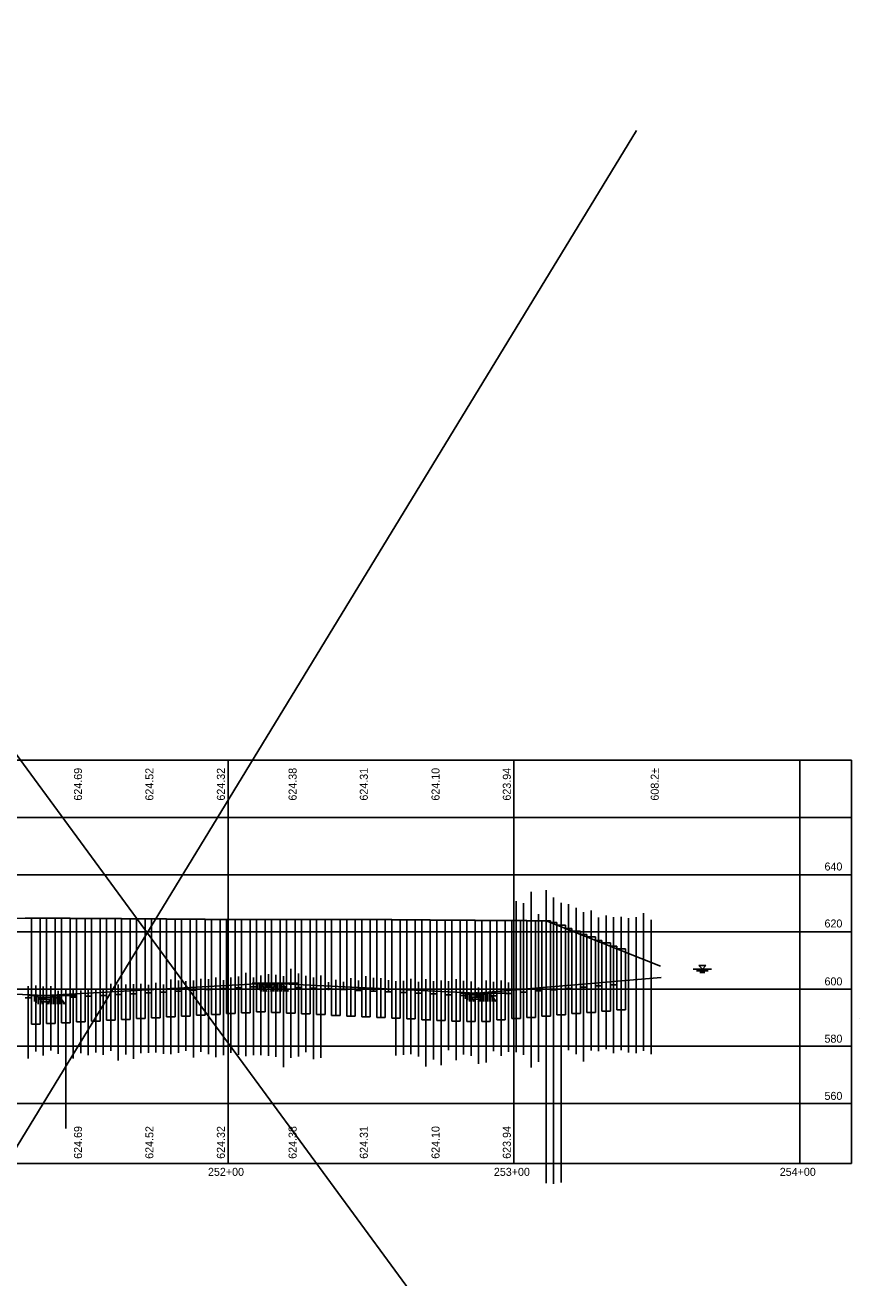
# Model space of a CAD drawing. Extents: x 2267596 to 2268160, y 712626 to 714793.
# Drawn here: x 2267867.7 to 2268159.8, y 712887.4 to 713325.6 of the extents above; entities that cross this region are included whole.
import ezdxf

# ---------------------------------------------------------------- set-up
doc = ezdxf.new("R2010")
doc.units = 0
for name, color, linetype in [('BR_P_Gen_Text', 7, 'Continuous'), ('BR_P_Sub_Deep_Object', 7, 'Continuous'), ('Default', 7, 'Continuous'), ('GE_X_Alignment', 7, 'Continuous'), ('PF_X_Ground_Line', 7, 'Continuous'), ('SC_Scratch1', 7, 'Continuous'), ('SC_Scratch9', 7, 'Continuous'), ('SH_Major_Grid_Line', 7, 'Continuous'), ('UT_P_Water_Cells', 7, 'Continuous'), ('XS_X_Ground_Line', 7, 'Continuous')]:
    doc.layers.add(name, color=color, linetype=linetype)

msp = doc.modelspace()

# ---------------------------------------------------------------- linework, layer by layer
at = {"layer": 'BR_P_Sub_Deep_Object'}
for p, q in [((2267867.74, 713013.25), (2267869.99, 713013.25)), ((2267869.99, 713013.25), (2267869.99, 712976.15)), ((2267869.99, 713013.23), (2267872.99, 713013.23)), ((2267872.99, 713013.23), (2267872.99, 712976.15)), ((2267872.99, 713013.21), (2267875.24, 713013.21)), ((2267875.24, 713013.21), (2267875.24, 712976.32)), ((2267875.24, 713013.2), (2267878.24, 713013.2)), ((2267878.24, 713013.2), (2267878.24, 712976.32)), ((2267878.24, 713013.18), (2267880.49, 713013.18)), ((2267880.49, 713013.18), (2267880.49, 712976.62)), ((2267880.49, 713013.17), (2267883.49, 713013.17)), ((2267883.49, 713013.17), (2267883.49, 712976.62)), ((2267883.49, 713013.15), (2267885.74, 713013.15)), ((2267885.74, 713013.15), (2267885.74, 712976.91)), ((2267885.74, 713013.14), (2267888.74, 713013.14)), ((2267888.74, 713013.14), (2267888.74, 712976.91)), ((2267888.74, 713013.12), (2267890.99, 713013.12)), ((2267890.99, 713013.12), (2267890.99, 712977.21)), ((2267890.99, 713013.1), (2267893.99, 713013.1)), ((2267893.99, 713013.1), (2267893.99, 712977.21)), ((2267893.99, 713013.08), (2267896.24, 713013.08)), ((2267896.24, 713013.08), (2267896.24, 712977.5)), ((2267896.24, 713013.07), (2267899.24, 713013.07)), ((2267899.24, 713013.07), (2267899.24, 712977.5)), ((2267899.24, 713013.05), (2267901.49, 713013.05)), ((2267901.49, 713013.05), (2267901.49, 712977.8)), ((2267901.49, 713013.03), (2267904.49, 713013.03)), ((2267904.49, 713013.03), (2267904.49, 712977.8)), ((2267904.49, 713013.01), (2267906.74, 713013.01)), ((2267906.74, 713013.01), (2267906.74, 712978.1)), ((2267906.74, 713013), (2267909.74, 713013)), ((2267909.74, 713013), (2267909.74, 712978.1)), ((2267909.74, 713012.98), (2267911.99, 713012.98)), ((2267911.99, 713012.98), (2267911.99, 712978.39)), ((2267911.99, 713012.96), (2267914.99, 713012.96)), ((2267914.99, 713012.96), (2267914.99, 712978.39)), ((2267914.99, 713012.94), (2267917.24, 713012.94)), ((2267917.24, 713012.94), (2267917.24, 712978.69)), ((2267917.24, 713012.92), (2267920.24, 713012.92)), ((2267920.24, 713012.92), (2267920.24, 712978.69)), ((2267920.24, 713012.9), (2267922.49, 713012.9)), ((2267922.49, 713012.9), (2267922.49, 712978.98)), ((2267922.49, 713012.88), (2267925.49, 713012.88)), ((2267925.49, 713012.88), (2267925.49, 712978.98)), ((2267925.49, 713012.86), (2267927.74, 713012.86)), ((2267927.74, 713012.86), (2267927.74, 712979.28)), ((2267927.74, 713012.84), (2267930.74, 713012.84)), ((2267930.74, 713012.84), (2267930.74, 712979.28)), ((2267930.74, 713012.81), (2267932.99, 713012.81)), ((2267932.99, 713012.81), (2267932.99, 712979.57)), ((2267932.99, 713012.8), (2267935.99, 713012.8)), ((2267935.99, 713012.8), (2267935.99, 712979.57)), ((2267935.99, 713012.77), (2267938.24, 713012.77)), ((2267938.24, 713012.77), (2267938.24, 712979.87)), ((2267938.24, 713012.76), (2267941.24, 713012.76)), ((2267941.24, 713012.76), (2267941.24, 712979.87)), ((2267941.24, 713012.76), (2267943.49, 713012.76)), ((2267943.49, 713012.77), (2267943.49, 712980.16)), ((2267943.49, 713012.77), (2267946.49, 713012.77)), ((2267946.49, 713012.77), (2267946.49, 712980.16)), ((2267946.49, 713012.77), (2267948.74, 713012.77)), ((2267948.74, 713012.78), (2267948.74, 712980.46)), ((2267948.74, 713012.78), (2267951.74, 713012.78)), ((2267951.74, 713012.79), (2267951.74, 712980.46)), ((2267951.74, 713012.79), (2267953.99, 713012.79)), ((2267953.99, 713012.79), (2267953.99, 712980.23)), ((2267953.99, 713012.79), (2267956.99, 713012.79)), ((2267956.99, 713012.8), (2267956.99, 712980.23)), ((2267956.99, 713012.8), (2267959.24, 713012.8)), ((2267959.24, 713012.81), (2267959.24, 712979.97)), ((2267959.24, 713012.81), (2267962.24, 713012.81)), ((2267962.24, 713012.81), (2267962.24, 712979.97)), ((2267962.24, 713012.81), (2267964.49, 713012.81)), ((2267964.49, 713012.81), (2267964.49, 712979.72)), ((2267964.49, 713012.81), (2267967.49, 713012.81)), ((2267967.49, 713012.81), (2267967.49, 712979.72)), ((2267967.49, 713012.8), (2267969.74, 713012.8)), ((2267969.74, 713012.8), (2267969.74, 712979.47)), ((2267969.74, 713012.79), (2267972.74, 713012.79)), ((2267972.74, 713012.79), (2267972.74, 712979.47)), ((2267972.74, 713012.78), (2267974.99, 713012.78)), ((2267974.99, 713012.78), (2267974.99, 712979.21)), ((2267974.99, 713012.78), (2267977.99, 713012.78)), ((2267977.99, 713012.78), (2267977.99, 712979.21)), ((2267977.99, 713012.77), (2267980.24, 713012.77)), ((2267980.24, 713012.77), (2267980.24, 712978.96)), ((2267980.24, 713012.76), (2267983.24, 713012.76)), ((2267983.24, 713012.76), (2267983.24, 712978.96)), ((2267983.24, 713012.75), (2267985.49, 713012.75)), ((2267985.49, 713012.75), (2267985.49, 712978.71)), ((2267985.49, 713012.75), (2267988.49, 713012.75)), ((2267988.49, 713012.75), (2267988.49, 712978.71)), ((2267988.49, 713012.74), (2267990.74, 713012.74)), ((2267990.74, 713012.74), (2267990.74, 712978.45)), ((2267990.74, 713012.72), (2267993.74, 713012.72)), ((2267993.74, 713012.72), (2267993.74, 712978.45)), ((2267993.74, 713012.7), (2267995.99, 713012.7)), ((2267995.99, 713012.7), (2267995.99, 712978.2)), ((2267995.99, 713012.68), (2267998.99, 713012.68)), ((2267998.99, 713012.68), (2267998.99, 712978.2)), ((2267998.99, 713012.65), (2268001.24, 713012.65)), ((2268001.24, 713012.65), (2268001.24, 712977.95)), ((2268001.24, 713012.63), (2268004.24, 713012.63)), ((2268004.24, 713012.63), (2268004.24, 712977.95)), ((2268004.24, 713012.61), (2268006.49, 713012.61)), ((2268006.49, 713012.61), (2268006.49, 712977.7)), ((2268006.49, 713012.59), (2268009.49, 713012.59)), ((2268009.49, 713012.59), (2268009.49, 712977.44)), ((2268009.49, 713012.57), (2268011.74, 713012.57)), ((2268011.74, 713012.57), (2268011.74, 712977.44)), ((2268011.74, 713012.55), (2268014.74, 713012.55)), ((2268014.74, 713012.55), (2268014.74, 712977.44)), ((2268014.74, 713012.52), (2268016.99, 713012.52)), ((2268016.99, 713012.52), (2268016.99, 712977.19)), ((2268016.99, 713012.51), (2268019.99, 713012.51)), ((2268019.99, 713012.51), (2268019.99, 712977.19)), ((2268019.99, 713012.49), (2268022.24, 713012.49)), ((2268022.24, 713012.49), (2268022.24, 712977.05)), ((2268022.24, 713012.48), (2268025.24, 713012.48)), ((2268025.24, 713012.48), (2268025.24, 712977.05)), ((2268025.24, 713012.46), (2268027.49, 713012.46)), ((2268027.49, 713012.46), (2268027.49, 712977.05)), ((2268027.49, 713012.44), (2268030.49, 713012.44)), ((2268030.49, 713012.44), (2268030.49, 712977.05)), ((2268030.49, 713012.42), (2268032.74, 713012.42)), ((2268032.74, 713012.42), (2268032.74, 712977.63)), ((2268032.74, 713012.41), (2268035.74, 713012.41)), ((2268035.74, 713012.41), (2268035.74, 712977.63)), ((2268035.74, 713012.39), (2268037.99, 713012.39)), ((2268037.99, 713012.39), (2268037.99, 712978.07)), ((2268037.99, 713012.37), (2268040.99, 713012.37)), ((2268040.99, 713012.37), (2268040.99, 712978.07)), ((2268040.99, 713012.36), (2268043.24, 713012.36)), ((2268043.24, 713012.36), (2268043.24, 712978.5)), ((2268043.24, 713012.34), (2268046.24, 713012.34)), ((2268046.24, 713012.34), (2268046.24, 712978.5)), ((2268046.24, 713012.32), (2268048.49, 713012.32)), ((2268048.49, 713012.32), (2268048.49, 712978.94)), ((2268048.49, 713012.3), (2268051.49, 713012.3)), ((2268051.49, 713012.3), (2268051.49, 712978.94)), ((2268051.49, 713011.7), (2268053.74, 713011.7)), ((2268053.74, 713011.7), (2268053.74, 712979.38)), ((2268053.74, 713010.81), (2268056.74, 713010.81)), ((2268056.74, 713010.81), (2268056.74, 712979.38)), ((2268056.74, 713009.62), (2268058.99, 713009.62)), ((2268058.99, 713009.62), (2268058.99, 712979.82)), ((2268058.99, 713008.73), (2268061.99, 713008.73)), ((2268061.99, 713008.73), (2268061.99, 712979.82)), ((2268061.99, 713007.54), (2268064.24, 713007.54)), ((2268064.24, 713007.54), (2268064.24, 712980.26)), ((2268064.24, 713006.64), (2268067.24, 713006.64)), ((2268067.24, 713006.64), (2268067.24, 712980.26)), ((2268067.24, 713005.45), (2268069.49, 713005.45)), ((2268069.49, 713005.45), (2268069.49, 712980.7)), ((2268069.49, 713004.56), (2268072.49, 713004.56)), ((2268072.49, 713004.56), (2268072.49, 712980.7)), ((2268072.49, 713003.37), (2268074.74, 713003.37)), ((2268074.74, 713003.37), (2268074.74, 712981.14)), ((2268074.74, 713002.48), (2268077.74, 713002.48)), ((2268077.74, 713002.48), (2268077.74, 712981.14)), ((2267951.74, 712989.46), (2267953.99, 712989.46)), ((2268067.24, 712989.51), (2268069.49, 712989.51)), ((2268072.49, 712989.95), (2268074.74, 712989.95)), ((2267869.99, 712985.34), (2267867.74, 712985.34)), ((2267875.24, 712985.15), (2267872.99, 712985.15)), ((2267878.24, 712985.32), (2267880.49, 712985.32)), ((2267883.49, 712985.62), (2267885.74, 712985.62)), ((2267888.74, 712985.91), (2267890.99, 712985.91)), ((2267893.99, 712986.21), (2267896.24, 712986.21)), ((2267899.24, 712986.5), (2267901.49, 712986.5)), ((2267904.49, 712986.8), (2267906.74, 712986.8)), ((2267909.74, 712987.1), (2267911.99, 712987.1)), ((2267914.99, 712987.39), (2267917.24, 712987.39)), ((2267920.24, 712987.69), (2267922.49, 712987.69)), ((2267925.49, 712987.98), (2267927.74, 712987.98)), ((2267930.74, 712988.28), (2267932.99, 712988.28)), ((2267935.99, 712988.57), (2267938.24, 712988.57)), ((2267941.24, 712988.87), (2267943.49, 712988.87)), ((2267946.49, 712989.16), (2267948.74, 712989.16)), ((2267959.24, 712989.23), (2267956.99, 712989.23)), ((2267964.49, 712988.97), (2267962.24, 712988.97)), ((2267969.74, 712988.72), (2267967.49, 712988.72)), ((2267974.99, 712988.47), (2267972.74, 712988.47)), ((2267980.24, 712988.21), (2267977.99, 712988.21)), ((2267985.49, 712987.96), (2267983.24, 712987.96)), ((2267990.74, 712987.71), (2267988.49, 712987.71)), ((2267995.99, 712987.45), (2267993.74, 712987.45)), ((2268001.24, 712987.2), (2267998.99, 712987.2)), ((2268006.49, 712986.95), (2268004.24, 712986.95)), ((2268011.74, 712986.7), (2268009.49, 712986.7)), ((2268016.99, 712986.44), (2268014.74, 712986.44)), ((2268022.24, 712986.19), (2268019.99, 712986.19)), ((2268025.24, 712986.05), (2268027.49, 712986.05)), ((2268030.49, 712986.05), (2268032.74, 712986.05)), ((2268035.74, 712986.88), (2268037.99, 712986.88)), ((2268040.99, 712987.32), (2268043.24, 712987.32)), ((2268046.24, 712987.76), (2268048.49, 712987.76)), ((2268051.49, 712988.19), (2268053.74, 712988.19)), ((2268056.74, 712988.63), (2268058.99, 712988.63)), ((2268061.99, 712989.07), (2268064.24, 712989.07)), ((2268069.49, 712980.7), (2268072.49, 712980.7)), ((2268074.74, 712981.14), (2268077.74, 712981.14)), ((2267872.99, 712976.15), (2267869.99, 712976.15)), ((2267875.24, 712976.32), (2267878.24, 712976.32)), ((2267880.49, 712976.62), (2267883.49, 712976.62)), ((2267885.74, 712976.91), (2267888.74, 712976.91)), ((2267890.99, 712977.21), (2267893.99, 712977.21)), ((2267896.24, 712977.5), (2267899.24, 712977.5)), ((2267901.49, 712977.8), (2267904.49, 712977.8)), ((2267906.74, 712978.1), (2267909.74, 712978.1)), ((2267911.99, 712978.39), (2267914.99, 712978.39)), ((2267917.24, 712978.69), (2267920.24, 712978.69)), ((2267922.49, 712978.98), (2267925.49, 712978.98)), ((2267927.74, 712979.28), (2267930.74, 712979.28)), ((2267932.99, 712979.57), (2267935.99, 712979.57)), ((2267938.24, 712979.87), (2267941.24, 712979.87)), ((2267943.49, 712980.16), (2267946.49, 712980.16)), ((2267948.74, 712980.46), (2267951.74, 712980.46)), ((2267956.99, 712980.23), (2267953.99, 712980.23)), ((2267962.24, 712979.97), (2267959.24, 712979.97)), ((2267967.49, 712979.72), (2267964.49, 712979.72)), ((2267972.74, 712979.47), (2267969.74, 712979.47)), ((2267977.99, 712979.21), (2267974.99, 712979.21)), ((2267983.24, 712978.96), (2267980.24, 712978.96)), ((2267988.49, 712978.71), (2267985.49, 712978.71)), ((2267993.74, 712978.45), (2267990.74, 712978.45)), ((2267998.99, 712978.2), (2267995.99, 712978.2)), ((2268004.24, 712977.95), (2268001.24, 712977.95)), ((2268009.49, 712977.7), (2268006.49, 712977.7)), ((2268014.74, 712977.44), (2268011.74, 712977.44)), ((2268019.99, 712977.19), (2268016.99, 712977.19)), ((2268022.24, 712977.05), (2268025.24, 712977.05)), ((2268027.49, 712977.05), (2268030.49, 712977.05)), ((2268032.74, 712977.63), (2268035.74, 712977.63)), ((2268037.99, 712978.07), (2268040.99, 712978.07)), ((2268043.24, 712978.5), (2268046.24, 712978.5)), ((2268048.49, 712978.94), (2268051.49, 712978.94)), ((2268053.74, 712979.38), (2268056.74, 712979.38)), ((2268058.99, 712979.82), (2268061.99, 712979.82)), ((2268064.24, 712980.26), (2268067.24, 712980.26))]:
    msp.add_line(p, q, dxfattribs=at)
at = {"layer": 'Default'}
for p, q in [((2267963.53, 712990.53), (2267947.14, 712990.53)), ((2267949.16, 712990.53), (2267949.16, 712988.47)), ((2267949.85, 712990.53), (2267949.85, 712988.04)), ((2267950.06, 712990.53), (2267952.34, 712987.58)), ((2267950.54, 712989.92), (2267950.54, 712987.58)), ((2267955.31, 712989.89), (2267950.54, 712989.89)), ((2267955.77, 712990.53), (2267953.64, 712987.58)), ((2267955.31, 712989.89), (2267955.31, 712987.58)), ((2267956, 712990.53), (2267956, 712987.58)), ((2267956.69, 712990.53), (2267956.69, 712987.58)), ((2267957.38, 712990.53), (2267957.38, 712987.58)), ((2267957.6, 712990.53), (2267959.88, 712987.58)), ((2267958.07, 712989.92), (2267958.07, 712987.58)), ((2267885.37, 712986.13), (2267868.98, 712986.13)), ((2267870.99, 712986.13), (2267870.99, 712984.07)), ((2267871.68, 712986.13), (2267871.68, 712983.64)), ((2267871.9, 712986.13), (2267874.18, 712983.18)), ((2267872.38, 712985.52), (2267872.38, 712983.18)), ((2267877.15, 712985.49), (2267872.38, 712985.49)), ((2267877.61, 712986.13), (2267875.48, 712983.18)), ((2267877.15, 712985.49), (2267877.15, 712983.18)), ((2267877.84, 712986.13), (2267877.84, 712983.18)), ((2267878.53, 712986.13), (2267878.53, 712983.18)), ((2267879.22, 712986.13), (2267879.22, 712983.18)), ((2267879.44, 712986.13), (2267881.72, 712983.18)), ((2267879.91, 712985.52), (2267879.91, 712983.18)), ((2267954.76, 712989.13), (2267951.14, 712989.13)), ((2267951.23, 712989.02), (2267951.23, 712987.58)), ((2267954.19, 712988.34), (2267951.75, 712988.34)), ((2267951.91, 712988.13), (2267951.91, 712987.58)), ((2267954.01, 712988.08), (2267954.01, 712987.58)), ((2267954.66, 712988.99), (2267954.66, 712987.58)), ((2267958.76, 712989.02), (2267958.76, 712987.58)), ((2267959.45, 712988.13), (2267959.45, 712987.58)), ((2268036.18, 712987.03), (2268019.79, 712987.03)), ((2268021.8, 712987.03), (2268021.8, 712984.97)), ((2268022.49, 712987.03), (2268022.49, 712984.54)), ((2268022.71, 712987.03), (2268024.99, 712984.08)), ((2268023.18, 712986.42), (2268023.18, 712984.08)), ((2268027.96, 712986.39), (2268023.18, 712986.39)), ((2268027.4, 712985.63), (2268023.79, 712985.63)), ((2268023.87, 712985.52), (2268023.87, 712984.08)), ((2268028.42, 712987.03), (2268026.28, 712984.08)), ((2268027.3, 712985.49), (2268027.3, 712984.08)), ((2268027.96, 712986.39), (2268027.96, 712984.08)), ((2268028.65, 712987.03), (2268028.65, 712984.08)), ((2268029.34, 712987.03), (2268029.34, 712984.08)), ((2268030.03, 712987.03), (2268030.03, 712984.08)), ((2268030.25, 712987.03), (2268032.52, 712984.08)), ((2268030.72, 712986.42), (2268030.72, 712984.08)), ((2268031.41, 712985.52), (2268031.41, 712984.08)), ((2267876.6, 712984.73), (2267872.98, 712984.73)), ((2267873.07, 712984.62), (2267873.07, 712983.18)), ((2267876.03, 712983.94), (2267873.59, 712983.94)), ((2267873.75, 712983.73), (2267873.75, 712983.18)), ((2267875.84, 712983.68), (2267875.84, 712983.18)), ((2267876.5, 712984.59), (2267876.5, 712983.18)), ((2267880.6, 712984.62), (2267880.6, 712983.18)), ((2267881.29, 712983.73), (2267881.29, 712983.18)), ((2268026.83, 712984.84), (2268024.4, 712984.84)), ((2268024.56, 712984.63), (2268024.56, 712984.08)), ((2268026.65, 712984.58), (2268026.65, 712984.08)), ((2268032.09, 712984.63), (2268032.09, 712984.08))]:
    msp.add_line(p, q, dxfattribs=at)
at = {"layer": 'GE_X_Alignment'}
for p, q in [((2267938.74, 712927.44), (2267938.74, 713068.43)), ((2268038.74, 712927.44), (2268038.74, 713068.43)), ((2268138.74, 712927.44), (2268138.74, 713068.43)), ((2267595.7, 713048.43), (2268156.77, 713048.43)), ((2267595.7, 713028.43), (2268156.77, 713028.43)), ((2267595.7, 713008.43), (2268156.77, 713008.43)), ((2267595.7, 712988.43), (2268156.77, 712988.43)), ((2267595.7, 712968.43), (2268156.77, 712968.43)), ((2267595.7, 712948.43), (2268156.77, 712948.43))]:
    msp.add_line(p, q, dxfattribs=at)
at = {"layer": 'PF_X_Ground_Line'}
msp.add_line((2268159.73, 712978.24), (2268159.78, 712978.24), dxfattribs=at)
at = {"layer": 'SC_Scratch1'}
for p, q in [((2267677.34, 713325.63), (2268155.15, 712674.91)), ((2267677.34, 712625.8), (2268081.64, 713288.8)), ((2268044.74, 713022.41), (2268044.74, 712961)), ((2268049.99, 713022.97), (2268049.99, 712920.58)), ((2268052.62, 712920.26), (2268052.62, 713020.46)), ((2268039.49, 712966.39), (2268039.49, 713019.11)), ((2268042.12, 712965.38), (2268042.12, 713018.44)), ((2268055.24, 712920.7), (2268055.24, 713018.53)), ((2268057.87, 712967.04), (2268057.87, 713018.13)), ((2268060.49, 712965.59), (2268060.49, 713016.8)), ((2268065.74, 712966.88), (2268065.74, 713015.87)), ((2268047.37, 713014.57), (2268047.37, 712962.94)), ((2268063.12, 712963.1), (2268063.12, 713015.33)), ((2268068.37, 712966.66), (2268068.37, 713013.47)), ((2268070.99, 712967.35), (2268070.99, 713014.13)), ((2268073.62, 712965.98), (2268073.62, 713013.6)), ((2268076.24, 712967), (2268076.24, 713013.73)), ((2268078.87, 712966.2), (2268078.87, 713013.2)), ((2268081.49, 712965.94), (2268081.49, 713013.6)), ((2268084.12, 712966.8), (2268084.12, 713014.93)), ((2268086.74, 712965.66), (2268086.74, 713012.67)), ((2267944.99, 712964.92), (2267944.99, 712994.15)), ((2267960.74, 712964.39), (2267960.74, 712995.55)), ((2267963.37, 712964.78), (2267963.37, 712993.83)), ((2267868.87, 712964.1), (2267868.87, 712989.43)), ((2267871.49, 712966.62), (2267871.49, 712989.64)), ((2267874.12, 712965.21), (2267874.12, 712989.34)), ((2267876.74, 712966.95), (2267876.74, 712989.4)), ((2267897.74, 712966.77), (2267897.74, 712990.23)), ((2267900.37, 712963.4), (2267900.37, 712990.02)), ((2267902.99, 712965.58), (2267902.99, 712990.02)), ((2267905.62, 712964.01), (2267905.62, 712990.12)), ((2267908.24, 712965.97), (2267908.24, 712990.23)), ((2267910.87, 712966.16), (2267910.87, 712989.86)), ((2267913.49, 712966.19), (2267913.49, 712990.59)), ((2267916.12, 712965.82), (2267916.12, 712989.96)), ((2267918.74, 712965.64), (2267918.74, 712991.73)), ((2267921.37, 712966.13), (2267921.37, 712991.42)), ((2267923.99, 712966.76), (2267923.99, 712991.21)), ((2267926.62, 712964.47), (2267926.62, 712991.36)), ((2267929.24, 712966.51), (2267929.24, 712992.04)), ((2267931.87, 712965.7), (2267931.87, 712991.89)), ((2267934.49, 712964.6), (2267934.49, 712992.41)), ((2267937.12, 712965.34), (2267937.12, 712991.57)), ((2267939.74, 712966.16), (2267939.74, 712992.46)), ((2267942.37, 712965.47), (2267942.37, 712992.79)), ((2267947.62, 712965.29), (2267947.62, 712992.45)), ((2267950.24, 712965.29), (2267950.24, 712993.14)), ((2267952.87, 712965.01), (2267952.87, 712993.62)), ((2267955.49, 712964.73), (2267955.49, 712993.41)), ((2267958.12, 712961.11), (2267958.12, 712992.94)), ((2267965.99, 712966.4), (2267965.99, 712993.04)), ((2267968.62, 712963.9), (2267968.62, 712992.41)), ((2267971.24, 712964.4), (2267971.24, 712993.18)), ((2267973.87, 712988.08), (2267973.87, 712990.83)), ((2267976.49, 712979.21), (2267976.49, 712991.59)), ((2267979.12, 712988.21), (2267979.12, 712990.97)), ((2267981.74, 712978.96), (2267981.74, 712992.28)), ((2267984.37, 712987.96), (2267984.37, 712991.45)), ((2267986.99, 712978.71), (2267986.99, 712992.93)), ((2267989.62, 712987.71), (2267989.62, 712992.38)), ((2267992.24, 712978.45), (2267992.24, 712992.19)), ((2267994.87, 712987.45), (2267994.87, 712991.55)), ((2267997.49, 712965.22), (2267997.49, 712991.19)), ((2268000.12, 712965.4), (2268000.12, 712991.28)), ((2268002.74, 712965.67), (2268002.74, 712992.01)), ((2268005.37, 712964.87), (2268005.37, 712990.91)), ((2268007.99, 712961.39), (2268007.99, 712991.92)), ((2268010.62, 712963.81), (2268010.62, 712991.19)), ((2268013.24, 712961.75), (2268013.24, 712991.37)), ((2268015.87, 712967.01), (2268015.87, 712991.19)), ((2268018.49, 712963.49), (2268018.49, 712991.83)), ((2268021.12, 712965.58), (2268021.12, 712991.27)), ((2268023.74, 712965.05), (2268023.74, 712991.01)), ((2268028.99, 712962.73), (2268028.99, 712991.36)), ((2268031.62, 712966.74), (2268031.62, 712990.99)), ((2268034.24, 712965.03), (2268034.24, 712991.38)), ((2268036.87, 712966.46), (2268036.87, 712990.72)), ((2267879.37, 712965.78), (2267879.37, 712987.78)), ((2267881.99, 712966.14), (2267881.99, 712988.35)), ((2267884.62, 712964.12), (2267884.62, 712988.14)), ((2267887.24, 712965.96), (2267887.24, 712987.87)), ((2267889.87, 712965.26), (2267889.87, 712988.02)), ((2267892.49, 712966.19), (2267892.49, 712988.23)), ((2267895.12, 712965.4), (2267895.12, 712987.99)), ((2268026.37, 712962.31), (2268026.37, 712989.02)), ((2267881.99, 712968.43), (2267881.99, 712939.7))]:
    msp.add_line(p, q, dxfattribs=at)
at = {"layer": 'SC_Scratch9'}
for p, q in [((2267952.95, 712990.31), (2267952.95, 712990.83)), ((2267874.79, 712985.91), (2267874.79, 712986.43)), ((2268025.6, 712986.81), (2268025.6, 712987.33))]:
    msp.add_line(p, q, dxfattribs=at)
at = {"layer": 'SH_Major_Grid_Line'}
for p, q in [((2268156.77, 713068.43), (2267595.7, 713068.43)), ((2268156.77, 712927.44), (2268156.77, 713068.43)), ((2268156.77, 712927.44), (2267595.7, 712927.44))]:
    msp.add_line(p, q, dxfattribs=at)
at = {"layer": 'UT_P_Water_Cells'}
for p, q in [((2268101.42, 712995.43), (2268107.89, 712995.43)), ((2268102.62, 712994.83), (2268106.69, 712994.83)), ((2268104.66, 712995.43), (2268103.39, 712996.7)), ((2268103.39, 712996.7), (2268105.92, 712996.7)), ((2268103.82, 712994.23), (2268105.49, 712994.23)), ((2268104.66, 712995.43), (2268105.92, 712996.7))]:
    msp.add_line(p, q, dxfattribs=at)
at = {"layer": 'XS_X_Ground_Line'}
for p, q in [((2268049.99, 713012.3), (2268090, 712996.43)), ((2268025.6, 712987.03), (2268090.2, 712992.43))]:
    msp.add_line(p, q, dxfattribs=at)
for points in [[(2267638.74, 713014.86), (2267663.74, 713014.82), (2267688.74, 713014.8), (2267713.74, 713014.58), (2267738.74, 713014.34), (2267788.74, 713013.84), (2267813.74, 713013.68), (2267838.74, 713013.51), (2267863.74, 713013.27), (2267888.74, 713013.12), (2267913.74, 713012.95), (2267938.74, 713012.75), (2267963.74, 713012.81), (2267988.74, 713012.74), (2268013.74, 713012.53), (2268049.99, 713012.3)], [(2267694.36, 712988.33), (2267751.31, 712991.63), (2267874.79, 712986.13), (2267952.95, 712990.53), (2268025.6, 712987.03)]]:
    msp.add_lwpolyline(points, dxfattribs=at)

# ---------------------------------------------------------------- texts
at = {"layer": 'BR_P_Gen_Text'}
for s, p in [('624.69', (2267887.66, 713054.34)), ('624.52', (2267912.63, 713054.34)), ('624.32', (2267937.64, 713054.34)), ('624.38', (2267962.72, 713054.34)), ('624.31', (2267987.64, 713054.34)), ('624.10', (2268012.72, 713054.34)), ('623.94', (2268037.66, 713054.34)), ('608.2±', (2268089.4, 713054.34)), ('624.69', (2267887.66, 712929.04)), ('624.52', (2267912.63, 712929.04)), ('624.32', (2267937.64, 712929.04)), ('624.38', (2267962.72, 712929.04)), ('624.31', (2267987.64, 712929.04)), ('624.10', (2268012.72, 712929.04)), ('623.94', (2268037.66, 712929.04))]:
    msp.add_text(s, height=2.8, rotation=90, dxfattribs=at).set_placement(p)
for s, p in [('640', (2268147.38, 713029.89)), ('620', (2268147.38, 713009.96)), ('600', (2268147.38, 712989.7)), ('580', (2268147.38, 712969.67)), ('560', (2268147.38, 712949.65)), ('252+00', (2267931.73, 712923.08)), ('253+00', (2268031.73, 712923.08)), ('254+00', (2268131.73, 712923.08))]:
    msp.add_text(s, height=2.8, dxfattribs=at).set_placement(p)

doc.saveas('drawing.dxf')
